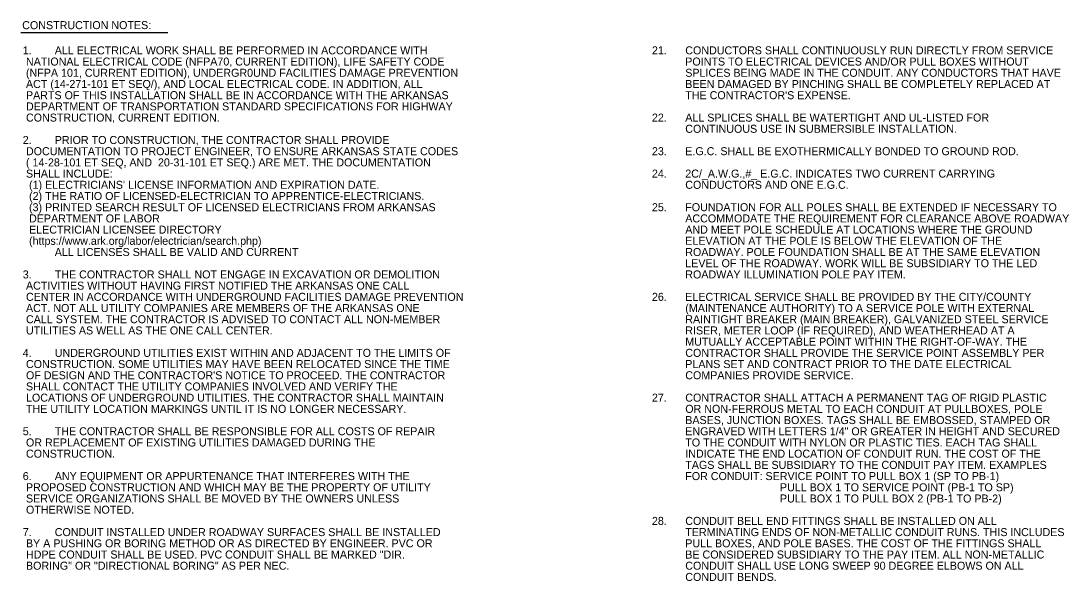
# Model space of a CAD drawing. Extents: x 478 to 2985, y 29 to 1032.
# Drawn here: x 2158 to 2977, y 473 to 910 of the extents above; entities that cross this region are included whole.
import ezdxf

# ---------------------------------------------------------------- set-up
doc = ezdxf.new("R2010")
doc.units = 0
doc.layers.add('E-ANNO-NOTE', color=7, linetype='Continuous')

msp = doc.modelspace()

# ---------------------------------------------------------------- linework, layer by layer
at = {"layer": 'E-ANNO-NOTE'}
msp.add_line((2158.31, 901.16), (2272.98, 901.16), dxfattribs=at)

# ---------------------------------------------------------------- texts
for s, rotation, p in [('CONSTRUCTION NOTES:', 0.04507, (2159.29, 903.68)), ('1.', 360, (2159.72, 884.01)), ('ALL ELECTRICAL WORK SHALL BE PERFORMED IN ACCORDANCE WITH ', 360, (2184.72, 884.01)), ('21.', 360, (2651.22, 884.01)), ('CONDUCTORS SHALL CONTINUOUSLY RUN DIRECTLY FROM SERVICE ', 360, (2677.26, 884.01)), ('NATIONAL ELECTRICAL CODE (NFPA70, CURRENT EDITION), LIFE SAFETY CODE ', 360, (2162.22, 875.26)), ('POINTS TO ELECTRICAL DEVICES AND/OR PULL BOXES WITHOUT ', 360, (2677.26, 875.26)), ('(NFPA 101, CURRENT EDITION), UNDERGR0UND FACILITIES DAMAGE PREVENTION ', 360, (2162.22, 866.51)), ('SPLICES BEING MADE IN THE CONDUIT. ANY CONDUCTORS THAT HAVE ', 360, (2677.26, 866.51)), ('ACT (14-271-101 ET SEQ/), AND LOCAL ELECTRICAL CODE. IN ADDITION, ALL ', 360, (2162.22, 857.76)), ('BEEN DAMAGED BY PINCHING SHALL BE COMPLETELY REPLACED AT ', 360, (2677.26, 857.76)), ('PARTS OF THIS INSTALLATION SHALL BE IN ACCORDANCE WITH THE ARKANSAS ', 360, (2162.22, 849.01)), ("THE CONTRACTOR'S EXPENSE.", 360, (2677.26, 849.01)), ('DEPARTMENT OF TRANSPORTATION STANDARD SPECIFICATIONS FOR HIGHWAY ', 360, (2162.22, 840.26)), ('CONSTRUCTION, CURRENT EDITION.', 360, (2162.22, 831.51)), ('22.', 360, (2651.22, 831.51)), ('ALL SPLICES SHALL BE WATERTIGHT AND UL-LISTED FOR ', 360, (2677.26, 831.51)), ('CONTINUOUS USE IN SUBMERSIBLE INSTALLATION.', 360, (2677.26, 822.76)), ('2.', 360, (2159.72, 814.01)), ('PRIOR TO CONSTRUCTION, THE CONTRACTOR SHALL PROVIDE ', 360, (2184.72, 814.01)), ('DOCUMENTATION TO PROJECT ENGINEER, TO ENSURE ARKANSAS STATE CODES ', 360, (2162.22, 805.26)), ('23.', 360, (2651.22, 805.26)), ('E.G.C. SHALL BE EXOTHERMICALLY BONDED TO GROUND ROD.', 360, (2677.26, 805.26)), ('( 14-28-101 ET SEQ, AND  20-31-101 ET SEQ.) ARE MET. THE DOCUMENTATION ', 360, (2162.22, 796.51)), ('2C/_A.W.G.,#_ E.G.C. INDICATES TWO CURRENT CARRYING ', 360, (2677.26, 787.76)), ('SHALL INCLUDE:', 360, (2162.22, 787.76)), ('24.', 360, (2651.22, 787.76)), ("(1) ELECTRICIANS' LICENSE INFORMATION AND EXPIRATION DATE.", 360, (2164.62, 779.01)), ('CONDUCTORS AND ONE E.G.C.', 360, (2677.26, 779.01)), ('(2) THE RATIO OF LICENSED-ELECTRICIAN TO APPRENTICE-ELECTRICIANS.', 360, (2164.62, 770.26)), ('(3) PRINTED SEARCH RESULT OF LICENSED ELECTRICIANS FROM ARKANSAS ', 360, (2164.62, 761.51)), ('25.', 360, (2651.22, 761.51)), ('FOUNDATION FOR ALL POLES SHALL BE EXTENDED IF NECESSARY TO ', 360, (2677.26, 761.51)), ('DEPARTMENT OF LABOR', 360, (2164.62, 752.76)), ('ACCOMMODATE THE REQUIREMENT FOR CLEARANCE ABOVE ROADWAY ', 360, (2677.26, 752.76)), ('ELECTRICIAN LICENSEE DIRECTORY ', 360, (2164.62, 744.01)), ('AND MEET POLE SCHEDULE AT LOCATIONS WHERE THE GROUND ', 360, (2677.26, 744.01)), ('(https://www.ark.org/labor/electrician/search.php)', 360, (2164.62, 735.26)), ('ELEVATION AT THE POLE IS BELOW THE ELEVATION OF THE ', 360, (2677.26, 735.26)), ('ALL LICENSES SHALL BE VALID AND CURRENT', 360, (2184.72, 726.51)), ('ROADWAY. POLE FOUNDATION SHALL BE AT THE SAME ELEVATION ', 360, (2677.26, 726.51)), ('LEVEL OF THE ROADWAY. WORK WILL BE SUBSIDIARY TO THE LED ', 360, (2677.26, 717.76)), ('3.', 360, (2159.72, 709.01)), ('THE CONTRACTOR SHALL NOT ENGAGE IN EXCAVATION OR DEMOLITION ', 360, (2184.72, 709.01)), ('ROADWAY ILLUMINATION POLE PAY ITEM.', 360, (2677.26, 709.01)), ('ACTIVITIES WITHOUT HAVING FIRST NOTIFIED THE ARKANSAS ONE CALL ', 360, (2162.22, 700.26)), ('CENTER IN ACCORDANCE WITH UNDERGROUND FACILITIES DAMAGE PREVENTION ', 360, (2162.22, 691.51)), ('26.', 360, (2651.22, 691.51)), ('ELECTRICAL SERVICE SHALL BE PROVIDED BY THE CITY/COUNTY ', 360, (2677.26, 691.51)), ('ACT. NOT ALL UTILITY COMPANIES ARE MEMBERS OF THE ARKANSAS ONE ', 360, (2162.22, 682.76)), ('(MAINTENANCE AUTHORITY) TO A SERVICE POLE WITH EXTERNAL ', 360, (2677.26, 682.76)), ('CALL SYSTEM. THE CONTRACTOR IS ADVISED TO CONTACT ALL NON-MEMBER ', 360, (2162.22, 674.01)), ('RAINTIGHT BREAKER (MAIN BREAKER), GALVANIZED STEEL SERVICE ', 360, (2677.26, 674.01)), ('UTILITIES AS WELL AS THE ONE CALL CENTER.', 360, (2162.22, 665.26)), ('RISER, METER LOOP (IF REQUIRED), AND WEATHERHEAD AT A ', 360, (2677.26, 665.26)), ('MUTUALLY ACCEPTABLE POINT WITHIN THE RIGHT-OF-WAY. THE ', 360, (2677.26, 656.51)), ('4.', 360, (2159.72, 647.76)), ('UNDERGROUND UTILITIES EXIST WITHIN AND ADJACENT TO THE LIMITS OF ', 360, (2184.72, 647.76)), ('CONTRACTOR SHALL PROVIDE THE SERVICE POINT ASSEMBLY PER ', 360, (2677.26, 647.76)), ('CONSTRUCTION. SOME UTILITIES MAY HAVE BEEN RELOCATED SINCE THE TIME ', 360, (2162.22, 639.01)), ('PLANS SET AND CONTRACT PRIOR TO THE DATE ELECTRICAL ', 360, (2677.26, 639.01)), ("OF DESIGN AND THE CONTRACTOR'S NOTICE TO PROCEED. THE CONTRACTOR ", 360, (2162.22, 630.26)), ('COMPANIES PROVIDE SERVICE.', 360, (2677.26, 630.26)), ('SHALL CONTACT THE UTILITY COMPANIES INVOLVED AND VERIFY THE ', 360, (2162.22, 621.51)), ('LOCATIONS OF UNDERGROUND UTILITIES. THE CONTRACTOR SHALL MAINTAIN ', 360, (2162.22, 612.76)), ('27.', 360, (2651.22, 612.76)), ('CONTRACTOR SHALL ATTACH A PERMANENT TAG OF RIGID PLASTIC ', 360, (2677.26, 612.76)), ('THE UTILITY LOCATION MARKINGS UNTIL IT IS NO LONGER NECESSARY.', 360, (2162.22, 604.01)), ('OR NON-FERROUS METAL TO EACH CONDUIT AT PULLBOXES, POLE ', 360, (2677.26, 604.01)), ('BASES, JUNCTION BOXES. TAGS SHALL BE EMBOSSED, STAMPED OR ', 360, (2677.26, 595.26)), ('5.', 360, (2159.72, 586.51)), ('THE CONTRACTOR SHALL BE RESPONSIBLE FOR ALL COSTS OF REPAIR ', 360, (2184.72, 586.51)), ('ENGRAVED WITH LETTERS 1/4" OR GREATER IN HEIGHT AND SECURED ', 360, (2677.26, 586.51)), ('OR REPLACEMENT OF EXISTING UTILITIES DAMAGED DURING THE ', 360, (2162.22, 577.76)), ('TO THE CONDUIT WITH NYLON OR PLASTIC TIES. EACH TAG SHALL ', 360, (2677.26, 577.76)), ('CONSTRUCTION.', 360, (2162.22, 569.01)), ('INDICATE THE END LOCATION OF CONDUIT RUN. THE COST OF THE ', 360, (2677.26, 569.01)), ('TAGS SHALL BE SUBSIDIARY TO THE CONDUIT PAY ITEM. EXAMPLES ', 360, (2677.26, 560.26)), ('6.', 360, (2159.72, 551.51)), ('ANY EQUIPMENT OR APPURTENANCE THAT INTERFERES WITH THE ', 360, (2184.72, 551.51)), ('FOR CONDUIT: SERVICE POINT TO PULL BOX 1 (SP TO PB-1)', 360, (2677.26, 551.51)), ('PROPOSED CONSTRUCTION AND WHICH MAY BE THE PROPERTY OF UTILITY ', 360, (2162.22, 542.76)), ('PULL BOX 1 TO SERVICE POINT (PB-1 TO SP)', 360, (2751.22, 542.76)), ('PULL BOX 1 TO PULL BOX 2 (PB-1 TO PB-2)', 360, (2751.22, 534.01)), ('SERVICE ORGANIZATIONS SHALL BE MOVED BY THE OWNERS UNLESS ', 360, (2162.22, 534.01)), ('OTHERWISE NOTED.', 360, (2162.22, 525.26)), ('28.', 360, (2651.22, 516.51)), ('CONDUIT BELL END FITTINGS SHALL BE INSTALLED ON ALL ', 360, (2677.26, 516.51)), ('7.', 360, (2159.72, 507.76)), ('CONDUIT INSTALLED UNDER ROADWAY SURFACES SHALL BE INSTALLED ', 360, (2184.72, 507.76)), ('TERMINATING ENDS OF NON-METALLIC CONDUIT RUNS. THIS INCLUDES ', 360, (2677.26, 507.76)), ('BY A PUSHING OR BORING METHOD OR AS DIRECTED BY ENGINEER. PVC OR ', 360, (2162.22, 499.01)), ('PULL BOXES, AND POLE BASES. THE COST OF THE FITTINGS SHALL ', 360, (2677.26, 499.01)), ('HDPE CONDUIT SHALL BE USED. PVC CONDUIT SHALL BE MARKED "DIR. ', 360, (2162.22, 490.26)), ('BE CONSIDERED SUBSIDIARY TO THE PAY ITEM. ALL NON-METALLIC ', 360, (2677.26, 490.26)), ('BORING" OR "DIRECTIONAL BORING" AS PER NEC.', 360, (2162.22, 481.51)), ('CONDUIT SHALL USE LONG SWEEP 90 DEGREE ELBOWS ON ALL ', 360, (2677.26, 481.51)), ('CONDUIT BENDS.', 360, (2677.26, 472.76))]:
    msp.add_text(s, height=6.25, rotation=rotation, dxfattribs=at).set_placement(p)

doc.saveas('drawing.dxf')
